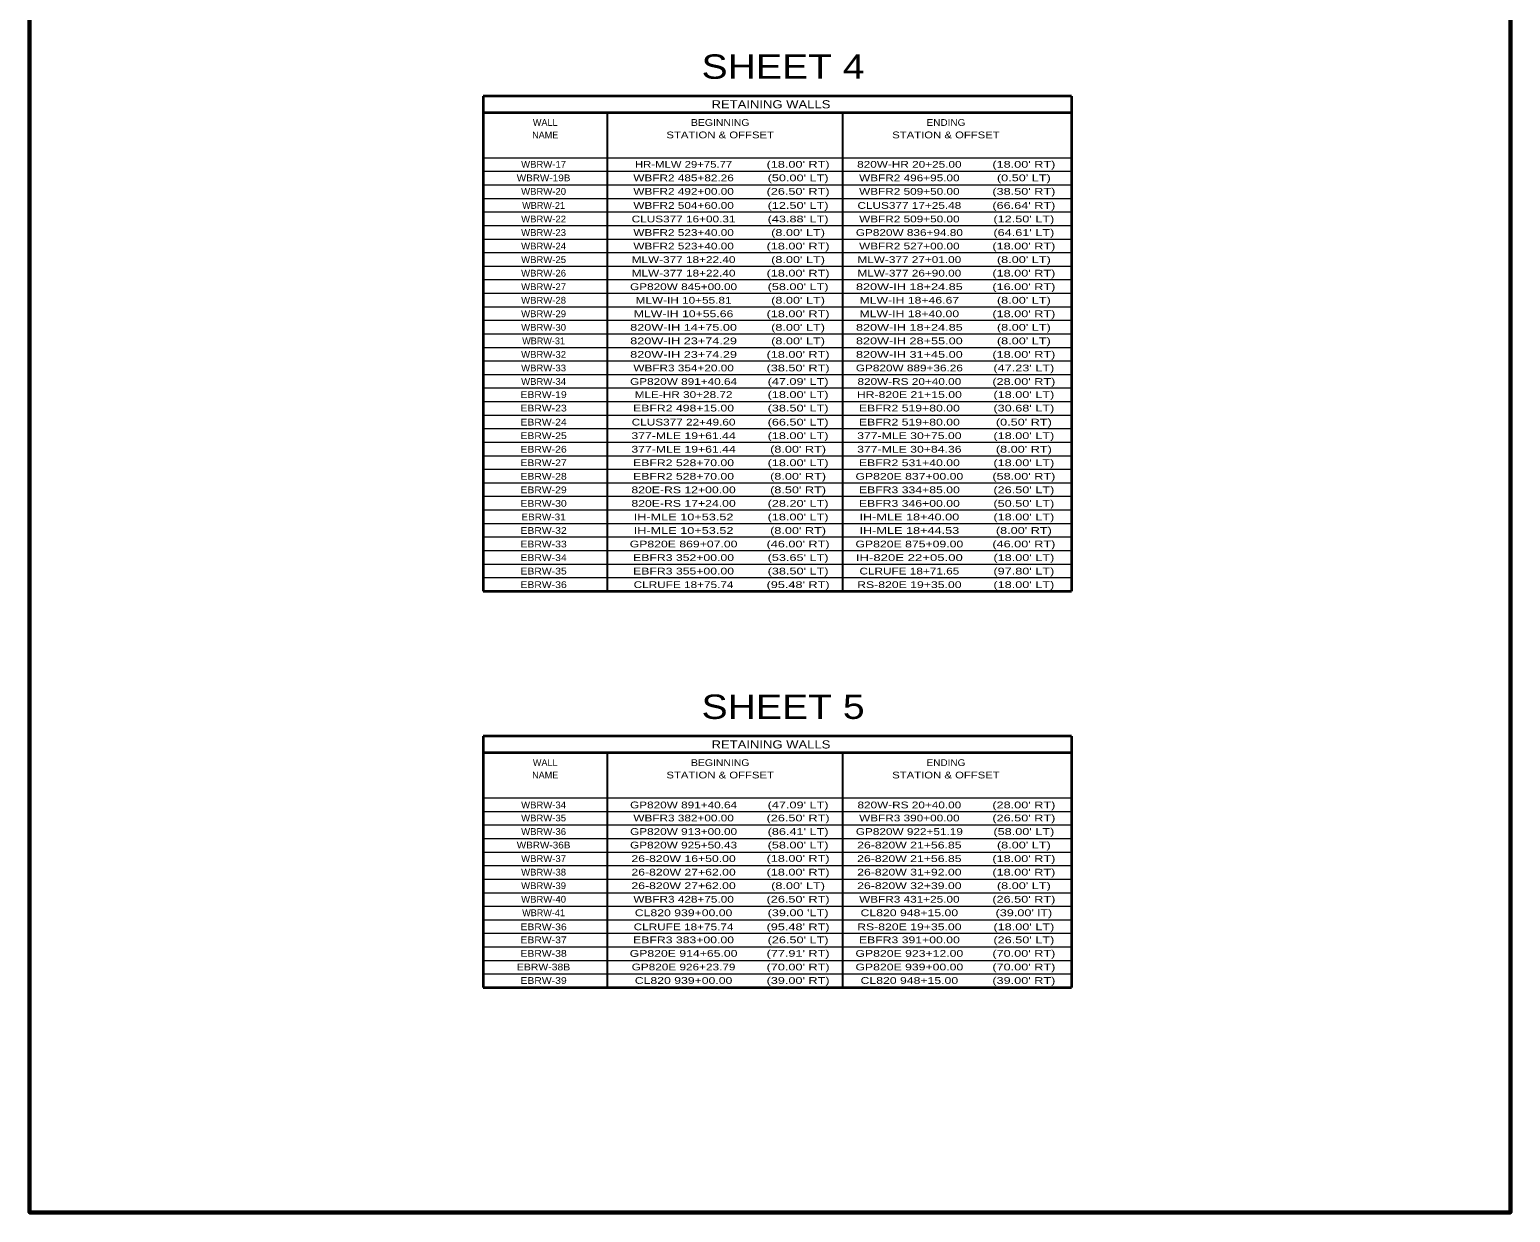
# Model space of a CAD drawing. Extents: x 2319482 to 2362028, y 6981189 to 6994467.
# Drawn here: x 2319482 to 2322105, y 6981189 to 6983285 of the extents above; entities that cross this region are included whole.
import ezdxf
from ezdxf.enums import TextEntityAlignment as Align

# ---------------------------------------------------------------- set-up
doc = ezdxf.new("R2010")
doc.units = 0
doc.header["$LTSCALE"] = 4.8
for name, color, linetype, lineweight in [('26', 7, 'Continuous', 13), ('45', 7, 'Continuous', 35), ('63', 7, 'Continuous', 60)]:
    doc.layers.add(name, color=color, linetype=linetype, lineweight=lineweight)

msp = doc.modelspace()

# ---------------------------------------------------------------- linework, layer by layer
at = {"layer": '26', "lineweight": 35}
for p, q in [((2321327.828, 6983166.748), (2320285.241, 6983166.748)), ((2320285.241, 6983166.748), (2320285.241, 6982289.615)), ((2321327.828, 6983166.748), (2321327.828, 6982289.615)), ((2320285.241, 6983137.948), (2321327.828, 6983137.948)), ((2320285.241, 6982289.615), (2321327.828, 6982289.615)), ((2321327.828, 6982032.371), (2320285.241, 6982032.371)), ((2320285.241, 6982032.371), (2320285.241, 6981587.238)), ((2321327.828, 6982032.371), (2321327.828, 6981587.238)), ((2320285.241, 6982003.571), (2321327.828, 6982003.571)), ((2320285.241, 6981587.238), (2321327.828, 6981587.238))]:
    msp.add_line(p, q, dxfattribs=at)
at = {"layer": '26', "lineweight": 25}
for p, q in [((2320505.241, 6983137.948), (2320505.241, 6982289.615)), ((2320921.935, 6983137.948), (2320921.935, 6982289.615)), ((2320505.241, 6982003.571), (2320505.241, 6981587.238)), ((2320921.935, 6982003.571), (2320921.935, 6981587.238))]:
    msp.add_line(p, q, dxfattribs=at)
at = {"layer": '26'}
for p, q in [((2320285.241, 6983057.615), (2321327.828, 6983057.615)), ((2320285.241, 6983033.615), (2321327.828, 6983033.615)), ((2320285.241, 6983009.615), (2321327.828, 6983009.615)), ((2320285.241, 6982985.615), (2321327.828, 6982985.615)), ((2320285.241, 6982961.615), (2321327.828, 6982961.615)), ((2320285.241, 6982937.615), (2321327.828, 6982937.615)), ((2320285.241, 6982913.615), (2321327.828, 6982913.615)), ((2320285.241, 6982889.615), (2321327.828, 6982889.615)), ((2320285.241, 6982865.615), (2321327.828, 6982865.615)), ((2320285.241, 6982841.615), (2321327.828, 6982841.615)), ((2320285.241, 6982817.615), (2321327.828, 6982817.615)), ((2320285.241, 6982793.615), (2321327.828, 6982793.615)), ((2320285.241, 6982769.615), (2321327.828, 6982769.615)), ((2320285.241, 6982745.615), (2321327.828, 6982745.615)), ((2320285.241, 6982721.615), (2321327.828, 6982721.615)), ((2320285.241, 6982697.615), (2321327.828, 6982697.615)), ((2320285.241, 6982673.615), (2321327.828, 6982673.615)), ((2320285.241, 6982649.615), (2321327.828, 6982649.615)), ((2320285.241, 6982625.615), (2321327.828, 6982625.615)), ((2320285.241, 6982601.615), (2321327.828, 6982601.615)), ((2320285.241, 6982577.615), (2321327.828, 6982577.615)), ((2320285.241, 6982553.615), (2321327.828, 6982553.615)), ((2320285.241, 6982529.615), (2321327.828, 6982529.615)), ((2320285.241, 6982505.615), (2321327.828, 6982505.615)), ((2320285.241, 6982481.615), (2321327.828, 6982481.615)), ((2320285.241, 6982457.615), (2321327.828, 6982457.615)), ((2320285.241, 6982433.615), (2321327.828, 6982433.615)), ((2320285.241, 6982409.615), (2321327.828, 6982409.615)), ((2320285.241, 6982385.615), (2321327.828, 6982385.615)), ((2320285.241, 6982361.615), (2321327.828, 6982361.615)), ((2320285.241, 6982337.615), (2321327.828, 6982337.615)), ((2320285.241, 6982313.615), (2321327.828, 6982313.615)), ((2320285.241, 6981923.238), (2321327.828, 6981923.238)), ((2320285.241, 6981899.238), (2321327.828, 6981899.238)), ((2320285.241, 6981875.238), (2321327.828, 6981875.238)), ((2320285.241, 6981851.238), (2321327.828, 6981851.238)), ((2320285.241, 6981827.238), (2321327.828, 6981827.238)), ((2320285.241, 6981803.238), (2321327.828, 6981803.238)), ((2320285.241, 6981779.238), (2321327.828, 6981779.238)), ((2320285.241, 6981755.238), (2321327.828, 6981755.238)), ((2320285.241, 6981731.238), (2321327.828, 6981731.238)), ((2320285.241, 6981707.238), (2321327.828, 6981707.238)), ((2320285.241, 6981683.238), (2321327.828, 6981683.238)), ((2320285.241, 6981659.238), (2321327.828, 6981659.238)), ((2320285.241, 6981635.238), (2321327.828, 6981635.238)), ((2320285.241, 6981611.238), (2321327.828, 6981611.238))]:
    msp.add_line(p, q, dxfattribs=at)
at = {"layer": '63'}
msp.add_lwpolyline([(2319481.784, 6985687.71), (2322105.179, 6985687.71), (2322105.179, 6981188.674), (2319481.784, 6981188.674)], close=True, dxfattribs=at)

# ---------------------------------------------------------------- texts
at = {"layer": '26'}
for s, height, width, p in [('SHEET 4', 43.2, 1.2, (2320816.684, 6983197.559)), ('RETAINING WALLS', 14.4, 1.2, (2320795.236, 6983145.15)), ('BEGINNING', 12, 1.15, (2320705.237, 6983114.075)), ('ENDING', 12, 1.1, (2321105.237, 6983114.073)), ('STATION & OFFSET', 12, 1.25, (2320705.236, 6983092.074)), ('STATION & OFFSET', 12, 1.25, (2321105.236, 6983092.075)), ('WBRW-17', 12, 1.05, (2320392.351, 6983039.97)), ('HR-MLW 29+75.77', 12, 1.25, (2320640.374, 6983039.97)), ("(18.00' RT)", 12, 1.4, (2320843.216, 6983039.969)), ('WBRW-19B', 12, 1.1, (2320392.35, 6983015.97)), ('WBFR2 485+82.26', 12, 1.3, (2320640.374, 6983015.97)), ("(50.00' LT)", 12, 1.4, (2320843.216, 6983015.969)), ('WBFR2 496+95.00', 12, 1.3, (2321040.374, 6983015.97)), ("(0.50' LT)", 12, 1.4, (2321243.217, 6983015.969)), ('WBRW-20', 12, 1.05, (2320392.351, 6982991.97)), ('WBFR2 492+00.00', 12, 1.3, (2320640.374, 6982991.97)), ('WBFR2 504+60.00', 12, 1.3, (2320640.374, 6982967.089)), ("(26.50' RT)", 12, 1.4, (2320843.216, 6982991.969)), ("(12.50' LT)", 12, 1.4, (2320843.216, 6982967.088)), ('CLUS377 17+25.48', 12, 1.3, (2321040.375, 6982967.089)), ('WBFR2 509+50.00', 12, 1.3, (2321040.374, 6982991.97)), ("(38.50' RT)", 12, 1.4, (2321243.216, 6982991.969)), ("(66.64' RT)", 12, 1.4, (2321243.216, 6982967.088)), ('WBRW-22', 12, 1.05, (2320392.351, 6982943.089)), ('CLUS377 16+00.31', 12, 1.3, (2320640.374, 6982943.089)), ("(43.88' LT)", 12, 1.4, (2320843.216, 6982943.088)), ('WBRW-23', 12, 1.05, (2320392.351, 6982919.089)), ('GP820W 836+94.80', 12, 1.3, (2321040.375, 6982919.089)), ("(64.61' LT)", 12, 1.4, (2321243.216, 6982919.088)), ('WBRW-24', 12, 1.05, (2320392.351, 6982895.089)), ('WBFR2 527+00.00', 12, 1.3, (2321040.374, 6982895.089)), ("(18.00' RT)", 12, 1.4, (2321243.216, 6982895.088)), ('WBRW-25', 12, 1.05, (2320392.351, 6982871.089)), ('MLW-377 18+22.40', 12, 1.3, (2320640.375, 6982871.089)), ("(8.00' LT)", 12, 1.4, (2320843.217, 6982871.088)), ('MLW-377 27+01.00', 12, 1.3, (2321040.375, 6982871.089)), ("(8.00' LT)", 12, 1.4, (2321243.217, 6982871.088)), ('WBRW-26', 12, 1.05, (2320392.35, 6982847.089)), ('MLW-377 18+22.40', 12, 1.3, (2320640.375, 6982847.089)), ("(18.00' RT)", 12, 1.4, (2320843.216, 6982847.088)), ('MLW-377 26+90.00', 12, 1.3, (2321040.375, 6982847.089)), ("(18.00' RT)", 12, 1.4, (2321243.216, 6982847.088)), ('WBRW-27', 12, 1.05, (2320392.351, 6982823.089)), ('GP820W 845+00.00', 12, 1.3, (2320640.375, 6982823.089)), ("(58.00' LT)", 12, 1.4, (2320843.216, 6982823.088)), ('820W-IH 18+24.85', 12, 1.4, (2321040.374, 6982823.089)), ("(16.00' RT)", 12, 1.4, (2321243.216, 6982823.088)), ('WBRW-28', 12, 1.05, (2320392.351, 6982799.089)), ('MLW-IH 10+55.81', 12, 1.3, (2320640.374, 6982799.089)), ("(8.00' LT)", 12, 1.4, (2320843.217, 6982799.088)), ('MLW-IH 18+46.67', 12, 1.35, (2321040.374, 6982799.089)), ("(8.00' LT)", 12, 1.4, (2321243.217, 6982799.088)), ('WBRW-29', 12, 1.05, (2320392.35, 6982775.089)), ('MLW-IH 10+55.66', 12, 1.35, (2320640.374, 6982775.089)), ("(18.00' RT)", 12, 1.4, (2320843.216, 6982775.088)), ('MLW-IH 18+40.00', 12, 1.35, (2321040.374, 6982775.089)), ("(18.00' RT)", 12, 1.4, (2321243.216, 6982775.088)), ('WBRW-30', 12, 1.05, (2320392.351, 6982751.089)), ('820W-IH 14+75.00', 12, 1.4, (2320640.374, 6982751.089)), ("(8.00' LT)", 12, 1.4, (2320843.217, 6982751.088)), ('820W-IH 18+24.85', 12, 1.4, (2321040.374, 6982751.089)), ("(8.00' LT)", 12, 1.4, (2321243.217, 6982751.088)), ('820W-IH 23+74.29', 12, 1.4, (2320640.374, 6982727.089)), ("(8.00' LT)", 12, 1.4, (2320843.217, 6982727.088)), ('820W-IH 28+55.00', 12, 1.4, (2321040.374, 6982727.089)), ("(8.00' LT)", 12, 1.4, (2321243.217, 6982727.088)), ('WBRW-32', 12, 1.05, (2320392.351, 6982703.089)), ('WBRW-33', 12, 1.05, (2320392.351, 6982679.089)), ('820W-IH 23+74.29', 12, 1.4, (2320640.374, 6982703.089)), ('WBFR3 354+20.00', 12, 1.3, (2320640.374, 6982679.089)), ("(18.00' RT)", 12, 1.4, (2320843.216, 6982703.088)), ("(38.50' RT)", 12, 1.4, (2320843.216, 6982679.088)), ('GP820W 889+36.26', 12, 1.3, (2321040.374, 6982679.089)), ('820W-IH 31+45.00', 12, 1.4, (2321040.374, 6982703.089)), ("(18.00' RT)", 12, 1.4, (2321243.216, 6982703.088)), ("(47.23' LT)", 12, 1.4, (2321243.216, 6982679.088)), ('WBRW-34', 12, 1.05, (2320392.351, 6982655.089)), ('GP820W 891+40.64', 12, 1.3, (2320640.375, 6982655.089)), ("(47.09' LT)", 12, 1.4, (2320843.216, 6982655.088)), ('820W-RS 20+40.00', 12, 1.3, (2321040.375, 6982655.089)), ("(28.00' RT)", 12, 1.4, (2321243.216, 6982655.088)), ('EBRW-19', 12, 1.15, (2320392.35, 6982631.97)), ('MLE-HR 30+28.72', 12, 1.3, (2320640.374, 6982631.97)), ("(18.00' LT)", 12, 1.4, (2320843.216, 6982631.969)), ('HR-820E 21+15.00', 12, 1.35, (2321040.375, 6982631.97)), ("(18.00' LT)", 12, 1.4, (2321243.216, 6982631.969)), ('EBRW-23', 12, 1.15, (2320392.351, 6982607.97)), ('EBFR2 498+15.00', 12, 1.35, (2320640.374, 6982607.97)), ("(38.50' LT)", 12, 1.4, (2320843.216, 6982607.969)), ('EBFR2 519+80.00', 12, 1.35, (2321040.374, 6982607.97)), ("(30.68' LT)", 12, 1.4, (2321243.216, 6982607.969)), ('EBRW-24', 12, 1.15, (2320392.351, 6982583.089)), ('CLUS377 22+49.60', 12, 1.3, (2320640.375, 6982583.089)), ("(66.50' LT)", 12, 1.4, (2320843.216, 6982583.088)), ('EBFR2 519+80.00', 12, 1.35, (2321040.374, 6982583.089)), ("(0.50' RT)", 12, 1.4, (2321243.217, 6982583.088)), ('EBRW-25', 12, 1.15, (2320392.351, 6982559.089)), ('377-MLE 19+61.44', 12, 1.35, (2320640.375, 6982559.089)), ("(18.00' LT)", 12, 1.4, (2320843.216, 6982559.088)), ('377-MLE 30+75.00', 12, 1.35, (2321040.375, 6982559.089)), ("(18.00' LT)", 12, 1.4, (2321243.216, 6982559.088)), ('EBRW-26', 12, 1.15, (2320392.35, 6982535.089)), ('377-MLE 19+61.44', 12, 1.35, (2320640.375, 6982535.089)), ("(8.00' RT)", 12, 1.4, (2320843.217, 6982535.088)), ('377-MLE 30+84.36', 12, 1.35, (2321040.374, 6982535.089)), ("(8.00' RT)", 12, 1.4, (2321243.217, 6982535.088)), ('EBRW-27', 12, 1.15, (2320392.351, 6982511.089)), ('EBFR2 528+70.00', 12, 1.35, (2320640.374, 6982511.089)), ("(18.00' LT)", 12, 1.4, (2320843.216, 6982511.088)), ('EBFR2 531+40.00', 12, 1.35, (2321040.374, 6982511.089)), ("(18.00' LT)", 12, 1.4, (2321243.216, 6982511.088)), ('EBRW-28', 12, 1.15, (2320392.351, 6982487.089)), ('EBFR2 528+70.00', 12, 1.35, (2320640.374, 6982487.089)), ("(8.00' RT)", 12, 1.4, (2320843.217, 6982487.088)), ('GP820E 837+00.00', 12, 1.35, (2321040.375, 6982487.089)), ("(58.00' RT)", 12, 1.4, (2321243.216, 6982487.088)), ('EBRW-29', 12, 1.15, (2320392.35, 6982463.089)), ('820E-RS 12+00.00', 12, 1.35, (2320640.375, 6982463.089)), ("(8.50' RT)", 12, 1.4, (2320843.217, 6982463.088)), ('EBFR3 334+85.00', 12, 1.35, (2321040.374, 6982463.089)), ("(26.50' LT)", 12, 1.4, (2321243.216, 6982463.088)), ('EBRW-30', 12, 1.15, (2320392.351, 6982439.089)), ('820E-RS 17+24.00', 12, 1.35, (2320640.375, 6982439.089)), ("(28.20' LT)", 12, 1.4, (2320843.216, 6982439.088)), ('EBFR3 346+00.00', 12, 1.35, (2321040.374, 6982439.089)), ("(50.50' LT)", 12, 1.4, (2321243.216, 6982439.088)), ('EBRW-32', 12, 1.15, (2320392.351, 6982391.089)), ('EBRW-31', 12, 1.1, (2320392.35, 6982415.089)), ('IH-MLE 10+53.52', 12, 1.4, (2320640.374, 6982415.089)), ('IH-MLE 10+53.52', 12, 1.4, (2320640.374, 6982391.089)), ("(18.00' LT)", 12, 1.4, (2320843.216, 6982415.088)), ("(8.00' RT)", 12, 1.4, (2320843.217, 6982391.088)), ('IH-MLE 18+40.00', 12, 1.4, (2321040.374, 6982415.089)), ('IH-MLE 18+44.53', 12, 1.4, (2321040.374, 6982391.089)), ("(18.00' LT)", 12, 1.4, (2321243.216, 6982415.088)), ("(8.00' RT)", 12, 1.4, (2321243.217, 6982391.088)), ('EBRW-33', 12, 1.15, (2320392.351, 6982367.089)), ('GP820E 869+07.00', 12, 1.35, (2320640.375, 6982367.089)), ("(46.00' RT)", 12, 1.4, (2320843.216, 6982367.088)), ('GP820E 875+09.00', 12, 1.35, (2321040.375, 6982367.089)), ("(46.00' RT)", 12, 1.4, (2321243.216, 6982367.088)), ('EBRW-34', 12, 1.15, (2320392.351, 6982343.089)), ('EBFR3 352+00.00', 12, 1.35, (2320640.374, 6982343.089)), ("(53.65' LT)", 12, 1.4, (2320843.216, 6982343.088)), ('IH-820E 22+05.00', 12, 1.45, (2321040.374, 6982343.089)), ("(18.00' LT)", 12, 1.4, (2321243.216, 6982343.088)), ('EBRW-35', 12, 1.15, (2320392.351, 6982319.089)), ('EBFR3 355+00.00', 12, 1.35, (2320640.374, 6982319.089)), ("(38.50' LT)", 12, 1.4, (2320843.216, 6982319.088)), ('CLRUFE 18+71.65', 12, 1.3, (2321040.374, 6982319.089)), ("(97.80' LT)", 12, 1.4, (2321243.216, 6982319.088)), ('EBRW-36', 12, 1.15, (2320392.35, 6982295.089)), ('CLRUFE 18+75.74', 12, 1.3, (2320640.374, 6982295.089)), ("(95.48' RT)", 12, 1.4, (2320843.216, 6982295.088)), ('RS-820E 19+35.00', 12, 1.35, (2321040.375, 6982295.089)), ("(18.00' LT)", 12, 1.4, (2321243.216, 6982295.088)), ('SHEET 5', 43.2, 1.2, (2320816.684, 6982063.181)), ('RETAINING WALLS', 14.4, 1.2, (2320795.236, 6982010.772)), ('BEGINNING', 12, 1.15, (2320705.237, 6981979.697)), ('ENDING', 12, 1.1, (2321105.237, 6981979.695)), ('STATION & OFFSET', 12, 1.25, (2320705.236, 6981957.696)), ('STATION & OFFSET', 12, 1.25, (2321105.236, 6981957.697)), ('WBRW-34', 12, 1.05, (2320392.351, 6981904.712)), ('GP820W 891+40.64', 12, 1.3, (2320640.375, 6981904.712)), ("(47.09' LT)", 12, 1.4, (2320843.216, 6981904.711)), ('820W-RS 20+40.00', 12, 1.3, (2321040.375, 6981904.712)), ("(28.00' RT)", 12, 1.4, (2321243.216, 6981904.711)), ('WBRW-35', 12, 1.05, (2320392.351, 6981881.592)), ('WBFR3 382+00.00', 12, 1.3, (2320640.374, 6981881.592)), ("(26.50' RT)", 12, 1.4, (2320843.216, 6981881.591)), ('WBFR3 390+00.00', 12, 1.3, (2321040.374, 6981881.592)), ("(26.50' RT)", 12, 1.4, (2321243.216, 6981881.591)), ('WBRW-36', 12, 1.05, (2320392.35, 6981857.592)), ('GP820W 913+00.00', 12, 1.3, (2320640.375, 6981857.592)), ("(86.41' LT)", 12, 1.4, (2320843.216, 6981857.591)), ('GP820W 922+51.19', 12, 1.3, (2321040.374, 6981857.592)), ("(58.00' LT)", 12, 1.4, (2321243.216, 6981857.591)), ('WBRW-36B', 12, 1.1, (2320392.35, 6981833.592)), ('GP820W 925+50.43', 12, 1.3, (2320640.375, 6981833.592)), ("(58.00' LT)", 12, 1.4, (2320843.216, 6981833.591)), ('26-820W 21+56.85', 12, 1.35, (2321040.375, 6981833.592)), ("(8.00' LT)", 12, 1.4, (2321243.217, 6981833.591)), ('WBRW-37', 12, 1.05, (2320392.351, 6981809.592)), ('26-820W 16+50.00', 12, 1.35, (2320640.375, 6981809.592)), ("(18.00' RT)", 12, 1.4, (2320843.216, 6981809.957)), ('26-820W 21+56.85', 12, 1.35, (2321040.375, 6981809.592)), ("(18.00' RT)", 12, 1.4, (2321243.216, 6981809.591)), ('WBRW-39', 12, 1.05, (2320392.35, 6981761.592)), ('WBRW-38', 12, 1.05, (2320392.351, 6981785.592)), ('26-820W 27+62.00', 12, 1.35, (2320640.375, 6981785.592)), ('26-820W 27+62.00', 12, 1.35, (2320640.375, 6981761.592)), ("(18.00' RT)", 12, 1.4, (2320843.216, 6981785.591)), ("(8.00' LT)", 12, 1.4, (2320843.217, 6981761.591)), ('26-820W 31+92.00', 12, 1.35, (2321040.375, 6981785.592)), ('26-820W 32+39.00', 12, 1.35, (2321040.375, 6981761.592)), ("(18.00' RT)", 12, 1.4, (2321243.216, 6981785.591)), ("(8.00' LT)", 12, 1.4, (2321243.217, 6981761.591)), ('WBRW-40', 12, 1.05, (2320392.351, 6981737.592)), ('WBFR3 428+75.00', 12, 1.3, (2320640.374, 6981737.592)), ("(26.50' RT)", 12, 1.4, (2320843.216, 6981737.591)), ('WBFR3 431+25.00', 12, 1.3, (2321040.374, 6981737.592)), ("(26.50' RT)", 12, 1.4, (2321243.216, 6981737.591)), ('CL820 939+00.00', 12, 1.35, (2320640.374, 6981713.592)), ("(39.00 'LT)", 12, 1.4, (2320843.216, 6981713.591)), ('CL820 948+15.00', 12, 1.35, (2321040.374, 6981713.592)), ("(39.00' lT)", 12, 1.4, (2321243.216, 6981713.591)), ('EBRW-36', 12, 1.15, (2320392.349, 6981688.712)), ('CLRUFE 18+75.74', 12, 1.3, (2320640.373, 6981688.712)), ("(95.48' RT)", 12, 1.4, (2320843.215, 6981688.711)), ('RS-820E 19+35.00', 12, 1.35, (2321040.374, 6981688.712)), ("(18.00' LT)", 12, 1.4, (2321243.215, 6981688.711)), ('EBRW-37', 12, 1.15, (2320392.35, 6981665.592)), ('EBFR3 383+00.00', 12, 1.35, (2320640.373, 6981665.592)), ("(26.50' LT)", 12, 1.4, (2320843.215, 6981665.591)), ('EBFR3 391+00.00', 12, 1.35, (2321040.373, 6981665.592)), ("(26.50' LT)", 12, 1.4, (2321243.215, 6981665.591)), ('EBRW-38', 12, 1.15, (2320392.35, 6981641.592)), ('GP820E 914+65.00', 12, 1.35, (2320640.374, 6981641.592)), ("(77.91' RT)", 12, 1.4, (2320843.215, 6981641.591)), ('GP820E 923+12.00', 12, 1.35, (2321040.374, 6981641.592)), ("(70.00' RT)", 12, 1.4, (2321243.215, 6981641.591)), ('EBRW-38B', 12, 1.15, (2320392.349, 6981617.592)), ('GP820E 926+23.79', 12, 1.3, (2320640.373, 6981617.592)), ("(70.00' RT)", 12, 1.4, (2320843.215, 6981617.591)), ('GP820E 939+00.00', 12, 1.35, (2321040.374, 6981617.592)), ("(70.00' RT)", 12, 1.4, (2321243.215, 6981617.591)), ('EBRW-39', 12, 1.15, (2320392.349, 6981593.593)), ('CL820 939+00.00', 12, 1.35, (2320640.373, 6981593.593)), ("(39.00' RT)", 12, 1.4, (2320843.215, 6981593.592)), ('CL820 948+15.00', 12, 1.35, (2321040.373, 6981593.593)), ("(39.00' RT)", 12, 1.4, (2321243.215, 6981593.592))]:
    msp.add_text(s, height=height, dxfattribs=dict(at, width=width)).set_placement(p, align=Align.CENTER)
for s, p in [('WALL', (2320395.236, 6983114.074)), ('NAME', (2320395.235, 6983092.074)), ('WBRW-21', (2320392.35, 6982967.089)), ('WBRW-31', (2320392.35, 6982727.089)), ('WALL', (2320395.236, 6981979.696)), ('NAME', (2320395.235, 6981957.696)), ('WBRW-41', (2320392.35, 6981713.592))]:
    msp.add_text(s, height=12, dxfattribs=at).set_placement(p, align=Align.CENTER)
at = {"layer": '45'}
for s, width, p in [('820W-HR 20+25.00', 1.3, (2321040.375, 6983039.97)), ("(18.00' RT)", 1.4, (2321243.216, 6983039.969)), ('WBFR2 509+50.00', 1.3, (2321040.374, 6982943.089)), ("(12.50' LT)", 1.4, (2321243.216, 6982943.088)), ('WBFR2 523+40.00', 1.3, (2320640.374, 6982919.089)), ("(8.00' LT)", 1.4, (2320843.217, 6982919.088)), ('WBFR2 523+40.00', 1.3, (2320640.374, 6982895.089)), ("(18.00' RT)", 1.4, (2320843.216, 6982895.088))]:
    msp.add_text(s, height=12, dxfattribs=dict(at, width=width)).set_placement(p, align=Align.CENTER)

doc.saveas('drawing.dxf')
